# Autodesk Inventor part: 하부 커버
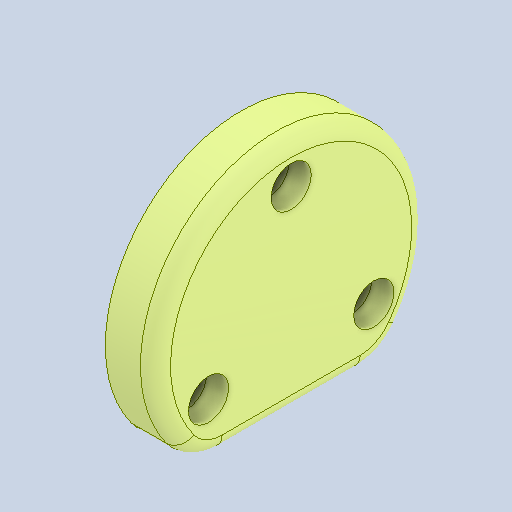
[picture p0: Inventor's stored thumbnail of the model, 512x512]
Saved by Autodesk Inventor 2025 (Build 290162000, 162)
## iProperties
Created: 2026-07
Part Number: 하부 커버
Material: 알루미늄 6061
Document SubType Name: Modeling
Designer: KDI
Density: 2.7 g/cm^3
Appearance: 기본값
Author: jhkim
Sending System: Autodesk Inventor 2027
Preprocessor: ST-DEVELOPER v20.1
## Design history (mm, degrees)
feature "솔리드1"
node "솔리드2"
